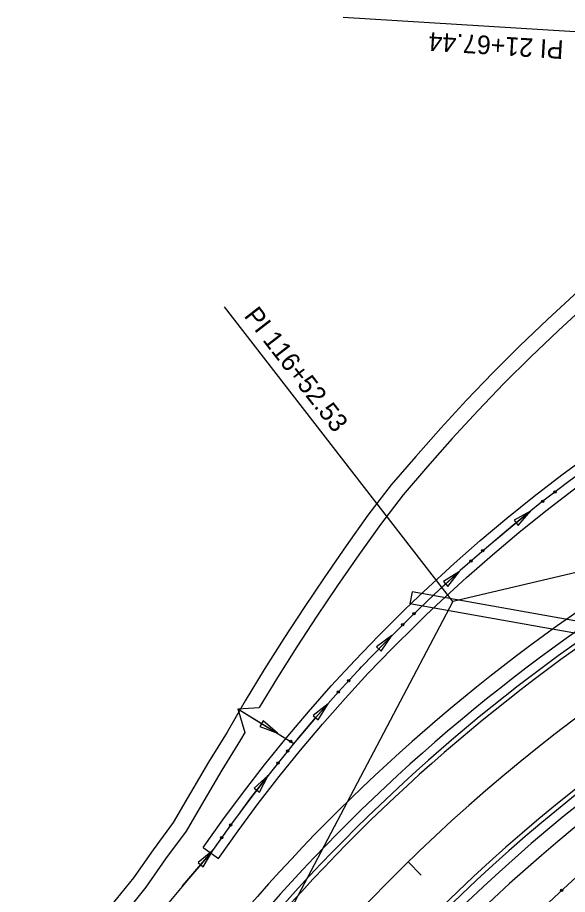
# Model space of a CAD drawing. Extents: x 979959 to 994833, y 1835619 to 1845316.
# Drawn here: x 981432.6 to 981609.6, y 1841642.4 to 1841924.8 of the extents above; entities that cross this region are included whole.
import ezdxf

# ---------------------------------------------------------------- set-up
doc = ezdxf.new("R2010")
doc.units = 0
for name, color, linetype in [('Future 5 Lane Construction Limits', 7, 'Continuous'), ('R_CONCRETE', 7, 'Continuous'), ('R_Drainage', 7, 'Continuous'), ('R_Horz Alg', 7, 'Continuous'), ('R_Horz Alg Annot', 7, 'Continuous'), ('R_Horz Alg Annot_Side Road', 7, 'Continuous'), ('R_Horz Alg Stationing', 7, 'Continuous'), ('R_Proposed Const Limits', 7, 'Continuous'), ('R_Proposed Road', 7, 'Continuous'), ('R_Special Ditch', 7, 'Continuous')]:
    doc.layers.add(name, color=color, linetype=linetype)

msp = doc.modelspace()

# ---------------------------------------------------------------- linework, layer by layer
at = {"layer": 'Future 5 Lane Construction Limits'}
msp.add_lwpolyline([(981658.43, 1841878.58), (981603.16, 1841827.55), (981594.24, 1841819.05), (981585.53, 1841810.37), (981577.05, 1841801.52), (981568.79, 1841792.54), (981560.76, 1841783.45), (981552.81, 1841774.24), (981545.35, 1841764.48), (981538.29, 1841754.58), (981531.44, 1841744.68), (981524.78, 1841734.75), (981518.29, 1841724.81), (981511.95, 1841714.82), (981505.86, 1841704.72), (981500.06, 1841694.67), (981494.01, 1841684.97), (981488.23, 1841675.05), (981482.62, 1841665.51), (981476.18, 1841656.72), (981469.86, 1841647.75), (981462.95, 1841639.14)], dxfattribs=at)
at = {"layer": 'R_CONCRETE'}
msp.add_line((981492.33, 1841657.44), (981497.23, 1841653.98), dxfattribs=at)
for points in [[(981492.33, 1841657.44), (981498.69, 1841666.42), (981505.27, 1841675.3), (981512.04, 1841684.05), (981519.02, 1841692.67), (981526.18, 1841701.15), (981533.54, 1841709.49), (981541.09, 1841717.68), (981548.82, 1841725.72), (981556.72, 1841733.61), (981559.85, 1841736.64), (981564.82, 1841741.35), (981573.08, 1841748.91), (981581.51, 1841756.31), (981590.1, 1841763.53), (981598.86, 1841770.59), (981607.78, 1841777.46), (981616.85, 1841784.15), (981626.07, 1841790.65), (981635.42, 1841796.96), (981636.42, 1841797.61), (981640.16, 1841800.04)], [(981497.23, 1841653.98), (981503.55, 1841662.9), (981510.05, 1841671.67), (981516.75, 1841680.32), (981523.64, 1841688.84), (981530.73, 1841697.23), (981538, 1841705.47), (981545.46, 1841713.57), (981553.1, 1841721.52), (981560.93, 1841729.33), (981564, 1841732.31), (981568.91, 1841736.96), (981577.08, 1841744.44), (981585.42, 1841751.76), (981593.92, 1841758.9), (981602.58, 1841765.87), (981611.39, 1841772.67), (981620.36, 1841779.28), (981629.48, 1841785.71), (981638.75, 1841791.96), (981639.7, 1841792.59), (981643.43, 1841795.01)]]:
    msp.add_lwpolyline(points, dxfattribs=at)
at = {"layer": 'R_Drainage'}
for p, q in [((981559.55, 1841739.85), (981558.85, 1841735.91)), ((981839.14, 1841689.98), (981559.55, 1841739.85)), ((981838.44, 1841686.04), (981558.85, 1841735.91)), ((981503.44, 1841702.1), (981521.54, 1841691)), ((981511.66, 1841698.3), (981510.56, 1841696.49)), ((981516.22, 1841694.26), (981511.66, 1841698.3)), ((981510.56, 1841696.49), (981516.22, 1841694.26))]:
    msp.add_line(p, q, dxfattribs=at)
msp.add_lwpolyline([(981503.44, 1841702.1), (981516.22, 1841694.26)], dxfattribs=at)
msp.add_circle((981520.51, 1841691.67), 0.375, dxfattribs=at)
at = {"layer": 'R_Horz Alg'}
msp.add_arc((981939.67, 1841262.61), 545.67, 103.2783, 152.2175, dxfattribs=at)
at = {"layer": 'R_Horz Alg Annot'}
for points in [[(981657.18, 1841917.39), (981537.41, 1841924.76)], [(981572.65, 1841736.66), (981499.18, 1841831.55)]]:
    msp.add_lwpolyline(points, dxfattribs=at)
at = {"layer": 'R_Horz Alg Annot_Side Road'}
for p, q in [((981814.34, 1841793.7), (981572.65, 1841736.66)), ((981572.65, 1841736.66), (981456.9, 1841516.96))]:
    msp.add_line(p, q, dxfattribs=at)
at = {"layer": 'R_Horz Alg Stationing'}
msp.add_lwpolyline([(981562.5, 1841648.61), (981558.31, 1841652.91)], dxfattribs=at)
at = {"layer": 'R_Proposed Const Limits'}
for q in [(981510.39, 1841702.55), (981505.74, 1841694.5)]:
    msp.add_line((981503.44, 1841702.1), q, dxfattribs=at)
for points in [[(981656.17, 1841869.69), (981606.58, 1841823.9), (981597.73, 1841815.47), (981589.1, 1841806.87), (981580.7, 1841798.1), (981572.51, 1841789.19), (981564.52, 1841780.16), (981556.69, 1841771.09), (981549.37, 1841761.51), (981542.38, 1841751.71), (981535.57, 1841741.87), (981528.95, 1841731.99), (981522.49, 1841722.1), (981516.2, 1841712.19), (981510.39, 1841702.55)], [(981637.09, 1841794.46), (981627.77, 1841788.18), (981618.6, 1841781.72), (981609.59, 1841775.06), (981600.72, 1841768.23), (981592.01, 1841761.22), (981583.46, 1841754.03), (981575.08, 1841746.67), (981566.87, 1841739.15), (981558.82, 1841731.47), (981550.96, 1841723.62), (981543.27, 1841715.63), (981535.77, 1841707.48), (981528.46, 1841699.19), (981521.33, 1841690.75), (981514.4, 1841682.18), (981507.66, 1841673.48), (981501.12, 1841664.66), (981494.78, 1841655.71), (981487.65, 1841647.5), (981480.68, 1841639.14)], [(981505.74, 1841694.5), (981504.35, 1841692.1), (981498.3, 1841682.39), (981492.54, 1841672.52), (981486.81, 1841662.76), (981480.24, 1841653.8), (981473.85, 1841644.74), (981466.95, 1841636.13)]]:
    msp.add_lwpolyline(points, dxfattribs=at)
at = {"layer": 'R_Proposed Road'}
for radius, start, end in [(527.67, 103.2783, 152.2175), (526.17, 103.2783, 152.2175), (573.17, 117.37429, 152.21752), (523.17, 103.2783, 152.2175), (568.17, 117.3743, 152.2175), (518.17, 103.2783, 152.2175), (565.17, 117.3743, 152.2175), (563.67, 117.3743, 152.2175)]:
    msp.add_arc((981939.67, 1841262.61), radius, start, end, dxfattribs=at)
at = {"layer": 'R_Special Ditch'}
for p, q in [((981597.71, 1841765.8), (981592.37, 1841762.87)), ((981593.7, 1841761.22), (981597.71, 1841765.8)), ((981592.37, 1841762.87), (981593.7, 1841761.22)), ((981574.78, 1841746.4), (981569.64, 1841743.13)), ((981571.07, 1841741.57), (981574.78, 1841746.4)), ((981569.64, 1841743.13), (981571.07, 1841741.57)), ((981552.99, 1841725.73), (981548.07, 1841722.14)), ((981549.59, 1841720.67), (981552.99, 1841725.73)), ((981548.07, 1841722.14), (981549.59, 1841720.67)), ((981532.5, 1841703.77), (981527.74, 1841699.97)), ((981529.32, 1841698.57), (981532.5, 1841703.77)), ((981527.74, 1841699.97), (981529.32, 1841698.57)), ((981513.26, 1841680.71), (981508.75, 1841676.62)), ((981510.42, 1841675.32), (981513.26, 1841680.71)), ((981508.75, 1841676.62), (981510.42, 1841675.32)), ((981495.47, 1841656.51), (981490.74, 1841652.67)), ((981492.34, 1841651.28), (981495.47, 1841656.51)), ((981490.74, 1841652.67), (981492.34, 1841651.28))]:
    msp.add_line(p, q, dxfattribs=at)
for points in [[(981609.54, 1841775.03), (981609.57, 1841775.05)], [(981586.13, 1841756.27), (981592.01, 1841761.22), (981597.71, 1841765.8)], [(981586.1, 1841756.25), (981586.13, 1841756.27)], [(981563.78, 1841736.2), (981566.87, 1841739.15), (981574.78, 1841746.4)], [(981563.75, 1841736.18), (981563.78, 1841736.2)], [(981542.61, 1841714.9), (981543.27, 1841715.63), (981550.96, 1841723.62), (981553.03, 1841725.69)], [(981542.58, 1841714.88), (981542.61, 1841714.9)], [(981522.72, 1841692.4), (981528.46, 1841699.19), (981532.5, 1841703.77)], [(981522.7, 1841692.37), (981522.72, 1841692.4)], [(981504.17, 1841668.78), (981507.66, 1841673.48), (981513.26, 1841680.71)], [(981703.94, 1841676.96), (981694.79, 1841675.26), (981685.61, 1841673.39), (981676.4, 1841671.34), (981667.16, 1841669.12), (981657.89, 1841666.73), (981648.61, 1841664.15), (981639.31, 1841661.4), (981629.99, 1841658.46), (981620.66, 1841655.34), (981613.73, 1841649.17), (981606.9, 1841642.91), (981600.17, 1841636.55)], [(981504.15, 1841668.75), (981504.17, 1841668.78)], [(981485.68, 1841645.14), (981487.65, 1841647.5), (981494.78, 1841655.71), (981495.39, 1841656.57)], [(981485.66, 1841645.11), (981485.68, 1841645.14)]]:
    msp.add_lwpolyline(points, dxfattribs=at)
for centre in [(981605.57, 1841772.01), (981601.6, 1841768.95), (981582.28, 1841753.04), (981578.51, 1841749.74), (981560.13, 1841732.76), (981556.55, 1841729.25), (981539.18, 1841711.23), (981535.79, 1841707.55), (981519.5, 1841688.55), (981516.35, 1841684.65), (981501.15, 1841664.76), (981498.26, 1841660.68), (981607.69, 1841643.69)]:
    msp.add_circle(centre, 0.375, dxfattribs=at)

# ---------------------------------------------------------------- texts
at = {"layer": 'R_Horz Alg Annot'}
for s, rotation, p in [('PI 21+67.44', 176.4802, (981608.46, 1841917.38)), ('PI 116+52.53', 307.7479, (981505.23, 1841828.64))]:
    msp.add_text(s, height=6, rotation=rotation, dxfattribs=at).set_placement(p)

doc.saveas('drawing.dxf')
